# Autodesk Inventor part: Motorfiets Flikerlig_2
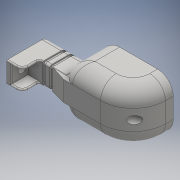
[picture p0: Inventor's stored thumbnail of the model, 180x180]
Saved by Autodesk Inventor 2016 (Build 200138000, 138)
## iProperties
Created: 2016-11
Part Number: Motorfiets Flikerlig_2
Material: Generic
Document SubType Name: Modeling
Designer: user
Density: 1 g/cm^3
Appearance: Default
Author: user
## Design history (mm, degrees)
sketch "Sketch1"
  geometry: L1 (0, 0)-(-62, 0); L2 (-62, 0)-(-62, -46); L3 (-62, -46)-(0, -46); L4 (0, -46)-(0, 0)
  constraints: 8 end point, 2 parallel, 1 horizontal, 1 perpendicular
  dimensions: "d0" = 62 distance of L3.end L2.end; "d1" = 46 distance of L2.end L1.end
extrude "Extrusion1" new body sketch "Sketch1" distance "d2" = 36; taper "d3" = 0 deg
sketch "Sketch2"
  geometry: L1 (13.5, 25.5)-(32.5, 25.5); L2 (32.5, 25.5)-(32.5, 4); L3 (32.5, 4)-(13.5, 4); L4 (13.5, 4)-(13.5, 25.5); L5 (0, 36)-(46, 36) reference; L6 (0, 0)-(46, 0) reference; L7 (0, 0)-(0, 36) reference; L8 (46, 0)-(46, 36) reference
  constraints: 8 end point, 2 parallel, 1 horizontal, 1 perpendicular
  dimensions: "d4" = 21.5 distance between parallel lines of L3 L1; "d8" = 10.5 distance between parallel lines of L5 L1; "d9" = 4 distance between parallel lines of L6 L3 (derived); "d10" = 46 distance between parallel lines of L7 L8 (derived); "d11" = 19 distance between parallel lines of L4 L2; "d12" = 13.5 distance between parallel lines of L7 L4; "d13" = 13.5 distance between parallel lines of L8 L2 (derived)
extrude "Extrusion2" join sketch "Sketch2" distance "d14" = 40; taper "d15" = 0 deg
sketch "Sketch3"
  geometry: L1 (0, 0)-(-40, 0) reference; L2 (0, 19)-(-40, 19) reference; L3 (-40, 0)-(-26, 0); L4 (-26, 0)-(-26, 19); L5 (-26, 19)-(-40, 19); L6 (-40, 19)-(-40, 0); 1 further point
  constraints: 8 end point, 2 parallel, 1 horizontal, 1 perpendicular, 1 point on line
  dimensions: "d16" = 14 distance between parallel lines of L6 L4
extrude "Extrusion3" join sketch "Sketch3" distance "d17" = 15; taper "d18" = 0 deg
sketch "Sketch4"
  geometry: L1 (1.5, 44.5)-(60.5, 44.5); L2 (60.5, 44.5)-(60.5, 1.5); L3 (60.5, 1.5)-(1.5, 1.5); L4 (1.5, 1.5)-(1.5, 44.5); L5 (62, 46)-(0, 46) reference; L6 (62, 0)-(62, 46) reference; L7 (0, 0)-(62, 0) reference; L8 (0, 46)-(0, 0) reference; L9 (2.5, 43.5)-(59.5, 43.5); L10 (59.5, 43.5)-(59.5, 2.5); L11 (59.5, 2.5)-(2.5, 2.5); L12 (2.5, 2.5)-(2.5, 43.5); C1 r 3 at (54, 23); C2 r 4.5 at (54, 23)
  constraints: 16 end point, 4 parallel, 2 centre point, 2 horizontal, 2 perpendicular, 1 coincident
  dimensions: "d19" = 1.5 distance between parallel lines of L5 L1; "d20" = 1.5 distance between parallel lines of L6 L2; "d21" = 1.5 distance between parallel lines of L7 L3; "d22" = 1.5 distance between parallel lines of L8 L4; "d23" = 6 diameter of C1; "d24" = 9 diameter of C2; "d25" = 8 distance from line of L6 C1.centre; "d26" = 1 distance between parallel lines of L1 L9; "d27" = 1 distance between parallel lines of L2 L10; "d28" = 1 distance between parallel lines of L3 L11; "d29" = 1 distance between parallel lines of L4 L12
extrude "Extrusion4" cut sketch "Sketch4" distance "d30" = 4; taper "d31" = 0 deg
extrude "Extrusion5" cut sketch "Sketch4" distance "d32" = 32; taper "d33" = 0 deg
extrude "Extrusion6" cut sketch "Sketch4" distance "d34" = 12; taper "d35" = 0 deg
fillet "Fillet1" dims "d36" = 26
fillet "Fillet2" dims "d37" = 29
fillet "Fillet3" dims "d38" = 12
fillet "Fillet4" dims "d39" = 12
fillet "Fillet5" dims "d40" = 12
fillet "Fillet6" dims "d41" = 12
fillet "Fillet7" dims "d42" = 12
fillet "Fillet8" dims "d43" = 12
fillet "Fillet9" dims "d44" = 14
sketch "Sketch5"
  geometry: L1 (-13, 5.5)-(-5, 5.5); L2 (-5, 5.5)-(-5, 3.5); L3 (-5, 3.5)-(-13, 3.5); L4 (-13, 3.5)-(-13, 5.5); L5 (0.5, 10.5)-(-18.5, 10.5) reference; L6 (0.5, 10.5)-(0, 0) reference; L7 (-18, 0)-(-18.5, 10.5) reference; L8 (14, -11.5)-(14, 10.5) reference; L9 (-32, 10.5)-(-32, -11.5) reference; 1 further point
  constraints: 8 end point, 2 parallel, 1 horizontal, 1 perpendicular
  dimensions: "d45" = 5 distance between parallel lines of L5 L1; "d46" = 2 distance between parallel lines of L1 L3; "d47" = 8 distance between parallel lines of L2 L4; "d48" = 18 distance between parallel lines of L6 L7 (derived); "d49" = 5 distance between parallel lines of L7 L4; "d50" = 5 distance between parallel lines of L6 L2 (derived)
extrude "Extrusion7" cut sketch "Sketch5" distance "d53" = 3; taper "d54" = 0 deg
sketch "Sketch6"
  geometry: L1 (0, 27)-(2.5, 27) reference; L2 (1.5, 13.5)-(1.5, 32.5) reference; L3 (2.5, 27)-(1.5, 27); L4 (1.5, 27)-(1.5, 19); L5 (1.5, 19)-(2.5, 19); L6 (2.5, 19)-(2.5, 27); 1 further point
  constraints: 8 end point, 2 parallel, 1 horizontal, 1 perpendicular, 1 point on line
  dimensions: "d164" = 8 distance between parallel lines of L1 L5
extrude "Extrusion8" cut sketch "Sketch6" distance "d55" = 1; taper "d56" = 0 deg
sketch "Sketch7"
  geometry: L1 (34, 0)-(0, 0) reference; L2 (15, 0)-(19, 0); L3 (19, 0)-(19, -2); L4 (19, -2)-(15, -2); L5 (15, -2)-(15, 0); L6 (48, -10.5)-(48, 0) reference; L7 (-14, 0)-(-14, -7) reference; 1 further point
  constraints: 8 end point, 2 parallel, 1 horizontal, 1 perpendicular, 1 point on line
  dimensions: "d57" = 4 distance of L3.end L4.end; "d58" = 2 distance of L2.end L3.end; "d59" = 29 distance between parallel lines of L6 L3; "d60" = 29 distance between parallel lines of L7 L5 (derived); "d61" = 62 distance between parallel lines of L6 L7 (derived)
extrude "Extrusion9" cut sketch "Sketch7" distance "d62" = 2; taper "d63" = 0 deg
sketch "Sketch8"
  geometry: 2 further points
hole "Hole1" sketch "Sketch8" at (0, 0) diameter "d64" = 3.5; stored, may be unused: countersink angle "d68" = 90 deg, drill point angle "d70" = 118 deg; dims "d65" = 6, "d66" = 4, "d67" = 2, "d69" = 8
workplane "Work Plane1"
sketch "Sketch9"
  geometry: C1 r 1.75 at (54, 23) reference; 2 further points
  constraints: 1 coincident
hole "Hole2" sketch "Sketch9" at (54, 23) diameter "d72" = 7; stored, may be unused: countersink angle "d76" = 90 deg, drill point angle "d78" = 118 deg; dims "d73" = 6, "d74" = 4, "d75" = 2, "d77" = 8
fillet "Fillet15" dims "d88" = 2
fillet "Fillet16" dims "d89" = 2
sketch "Sketch10"
  geometry: L1 (-24.197, 36.5)-(14, 36.5) reference; L2 (-3.2, 36.5)-(-5.6, 36.5); L3 (-5.6, 36.5)-(-5.6, 15); L4 (-5.6, 15)-(-3.2, 15); L5 (-3.2, 15)-(-3.2, 36.5); L6 (-9.6, 36.5)-(-12, 36.5); L7 (-12, 36.5)-(-12, 15); L8 (-12, 15)-(-9.6, 15); L9 (-9.6, 15)-(-9.6, 36.5); L10 (-26, 36.5)-(-26, 47) reference; 3 further points
  constraints: 16 end point, 4 parallel, 2 horizontal, 2 perpendicular, 2 point on line
  dimensions: "d91" = 2.4 distance between parallel lines of L9 L7; "d92" = 2.4 distance between parallel lines of L5 L3; "d93" = 14 distance between parallel lines of L10 L7; "d94" = 4 distance between parallel lines of L9 L3
sketch "Sketch11"
  geometry: L1 (26, 19)-(23.6, 19); L2 (23.6, 19)-(23.6, 0); L3 (23.6, 0)-(26, 0); L4 (26, 0)-(26, 19); L5 (40, 18.5)-(40, 0.5) reference; L6 (19.6, 19)-(17.2, 19); L7 (17.2, 19)-(17.2, 0); L8 (17.2, 0)-(19.6, 0); L9 (19.6, 0)-(19.6, 19); 1 further point
  constraints: 16 end point, 4 parallel, 2 horizontal, 2 perpendicular
  dimensions: "d95" = 2.4 distance between parallel lines of L2 L4; "d98" = 14 distance between parallel lines of L5 L4; "d99" = 4 distance between parallel lines of L2 L9; "d100" = 2.4 distance between parallel lines of L9 L7
sketch "Sketch12"
  geometry: L1 (38.197, 36.5)-(0, 36.5) reference; L2 (26, 36.5)-(23.6, 36.5); L3 (23.6, 36.5)-(23.6, 15); L4 (23.6, 15)-(26, 15); L5 (26, 15)-(26, 36.5); L6 (40, 47)-(40, 11) reference; L7 (19.6, 36.5)-(17.2, 36.5); L8 (17.2, 36.5)-(17.2, 15); L9 (17.2, 15)-(19.6, 15); L10 (19.6, 15)-(19.6, 36.5); 5 further points; 1 other entity
  constraints: 16 end point, 4 parallel, 2 horizontal, 2 perpendicular, 2 point on line, 1 other
  dimensions: "d102" = 2.4 distance between parallel lines of L5 L3; "d103" = 14 distance between parallel lines of L6 L5; "d104" = 2.4 distance between parallel lines of L8 L10; "d105" = 4 distance between parallel lines of L3 L10
workplane "Work Plane2"
sketch "Sketch13"
  geometry: L1 (38.197, 19)-(0, 19) reference; L2 (38.197, 0)-(0, 0) reference; L3 (26, 19)-(23.6, 19); L4 (23.6, 19)-(23.6, 0); L5 (23.6, 0)-(26, 0); L6 (26, 0)-(26, 19); L7 (19.6, 19)-(17.2, 19); L8 (17.2, 19)-(17.2, 0); L9 (17.2, 0)-(19.6, 0); L10 (19.6, 0)-(19.6, 19); 2 further points
  constraints: 16 end point, 4 parallel, 4 point on line, 2 horizontal, 2 perpendicular
  dimensions: "d107" = 2.4 distance between parallel lines of L6 L4; "d108" = 2.4 distance between parallel lines of L8 L10; "d109" = 4 distance between parallel lines of L4 L10
extrude "Extrusion10" cut sketch "Sketch12" distance "d111" = 1; taper "d112" = 0 deg
extrude "Extrusion11" cut sketch "Sketch11" distance "d113" = 1; taper "d114" = 0 deg
extrude "Extrusion12" cut sketch "Sketch10" distance "d115" = 1; taper "d116" = 0 deg
extrude "Extrusion13" cut sketch "Sketch13" distance "d117" = 1; taper "d118" = 0 deg
loft "Loft2" dims "d120" = 0, "d121" = 90 deg, "d122" = 0, "d123" = 90 deg
  node "Edges3"
  node "Edges4"
fillet "Fillet22" dims "d127" = 5
fillet "Fillet23" dims "d128" = 5
fillet "Fillet24" dims "d129" = 2
fillet "Fillet27" dims "d132" = 5
sketch "Sketch14"
  geometry: L1 (19, -15)-(0, -15) reference; L2 (0, 0)-(19, 0) reference; L3 (19, -15)-(17, -15); L4 (17, -15)-(17, 0); L5 (17, 0)-(19, 0); L6 (19, 0)-(19, -15); L7 (0, -15)-(2, -15); L8 (2, -15)-(2, 0); L9 (2, 0)-(0, 0); L10 (0, 0)-(0, -15); L11 (17, -15)-(2, -15); L12 (2, -15)-(2, 0); L13 (2, 0)-(17, 0); L14 (17, 0)-(17, -15); 1 further point
  constraints: 24 end point, 6 parallel, 3 horizontal, 3 perpendicular, 2 point on line
  dimensions: "d133" = 2 distance of L4.end L5.end; "d134" = 2 distance of L9.end L8.end
extrude "Extrusion14" cut sketch "Sketch14" distance "d135" = 10; taper "d136" = 0 deg
fillet "Fillet28" dims "d137" = 5
fillet "Fillet29" dims "d138" = 2
fillet "Fillet30" dims "d139" = 1
fillet "Fillet31" dims "d140" = 1
sketch "Sketch15"
  geometry: L1 (27.5, 25.5)-(18.5, 25.5) reference; L2 (32.5, 20.5)-(32.5, -10) reference; L3 (13.5, 20.5)-(13.5, -10) reference; 2 further points
  dimensions: "d142" = 8 distance from line of L1 point (23, 17.5); "d143" = 9.5 distance from line of L2 point (23, 17.5); "d144" = 9.5 distance from line of L3 point (23, 17.5) (derived)
hole "Hole3" sketch "Sketch15" at (23, 17.5) diameter "d145" = 6; stored, may be unused: countersink angle "d149" = 90 deg, drill point angle "d151" = 118 deg; dims "d146" = 6, "d147" = 4, "d148" = 2, "d150" = 44
sketch "Sketch16"
  geometry: L1 (31.5, -11)-(14.5, -11) reference; L2 (32.5, 20.5)-(32.5, -10) reference; L3 (13.5, 20.5)-(13.5, -10) reference; 2 further points
  dimensions: "d152" = 9.5 distance from line of L1 point (23, -1.5); "d153" = 9.5 distance from line of L2 point (23, -1.5); "d154" = 9.5 distance from line of L3 point (23, -1.5) (derived)
hole "Hole4" sketch "Sketch16" at (23, -1.5) diameter "d155" = 7; stored, may be unused: countersink angle "d159" = 90 deg, drill point angle "d161" = 118 deg; dims "d156" = 6, "d157" = 4, "d158" = 2, "d160" = 4
fillet "Fillet32" dims "d162" = 8
fillet "Fillet33" dims "d163" = 8
body "Solid1"
other parameters: "d71" = -3, "d106" = -21.5
